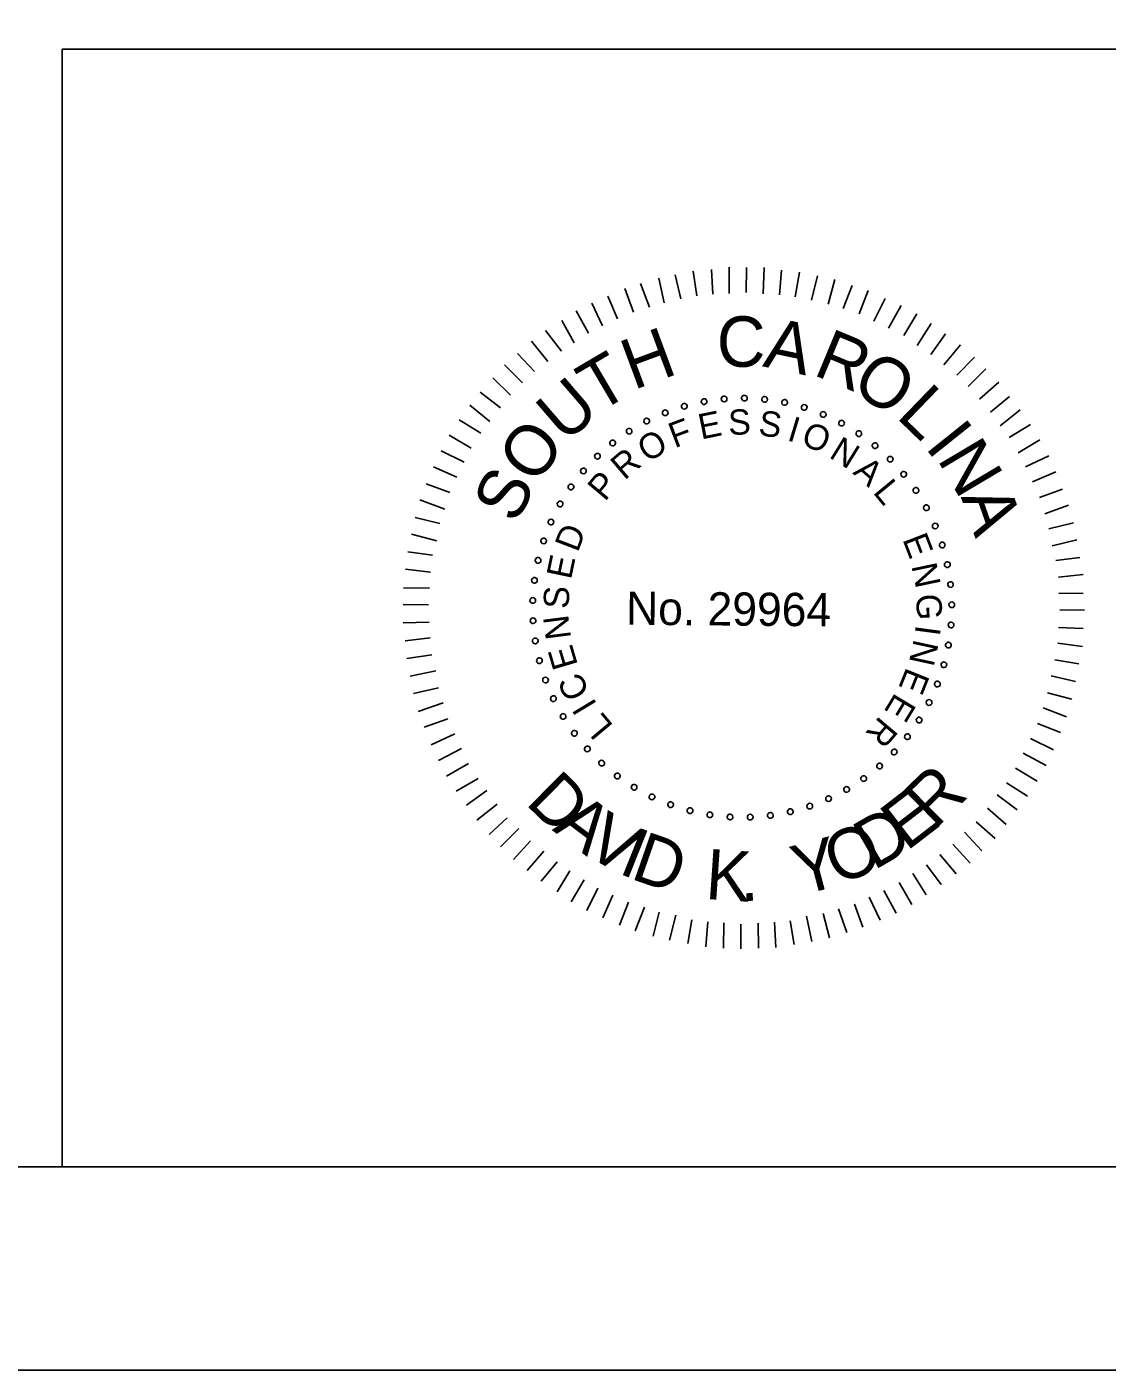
# Model space of a CAD drawing. Extents: x -55.6 to -19.5, y -5.1 to 16.9.
# Drawn here: x -33.037 to -30.378, y -5.092 to -1.787 of the extents above; entities that cross this region are included whole.
import ezdxf

# ---------------------------------------------------------------- set-up
doc = ezdxf.new("R2010")
doc.units = 0
for name, color, linetype in [('BR_BORDER LINES', 7, 'Continuous'), ('BR_TEXT', 7, 'Continuous'), ('Level 31', 7, 'Continuous')]:
    doc.layers.add(name, color=color, linetype=linetype)

msp = doc.modelspace()

# ---------------------------------------------------------------- linework, layer by layer
at = {"layer": 'BR_BORDER LINES'}
for p, q in [((-32.9495, -1.8415), (-27.5843, -1.8415)), ((-32.9495, -4.5916), (-32.9495, -1.8415)), ((-53.7501, -4.5917), (-20.084, -4.5917))]:
    msp.add_line(p, q, dxfattribs=at)
at = {"layer": 'BR_TEXT'}
for p, q in [((-31.3088, -2.4423), (-31.3083, -2.3779)), ((-31.2667, -2.4401), (-31.2662, -2.3783)), ((-31.2247, -2.443), (-31.2224, -2.3786)), ((-31.4686, -2.4658), (-31.4818, -2.4048)), ((-31.4273, -2.4559), (-31.4415, -2.3966)), ((-31.3878, -2.4485), (-31.3967, -2.3875)), ((-31.3483, -2.4445), (-31.3521, -2.3836)), ((-31.1844, -2.4459), (-31.1796, -2.385)), ((-31.1458, -2.4505), (-31.135, -2.3897)), ((-31.1055, -2.4586), (-31.0913, -2.3994)), ((-31.0645, -2.4692), (-31.0485, -2.4084)), ((-31.5443, -2.4884), (-31.5653, -2.4299)), ((-31.5048, -2.4758), (-31.5266, -2.4182)), ((-31.0276, -2.4798), (-31.0057, -2.4225)), ((-30.9883, -2.493), (-30.9663, -2.4348)), ((-31.6201, -2.5221), (-31.6463, -2.4661)), ((-31.5831, -2.5052), (-31.6067, -2.4493)), ((-30.9524, -2.5105), (-30.9245, -2.4549)), ((-30.9165, -2.5279), (-30.8851, -2.4724)), ((-31.69, -2.5636), (-31.7204, -2.5092)), ((-31.6546, -2.5398), (-31.685, -2.4855)), ((-30.8788, -2.5463), (-30.8466, -2.4924)), ((-31.721, -2.5848), (-31.7601, -2.5338)), ((-30.8456, -2.5705), (-30.8117, -2.5167)), ((-30.8123, -2.5923), (-30.7758, -2.5419)), ((-31.7547, -2.6102), (-31.7946, -2.5601)), ((-30.7799, -2.6183), (-30.7392, -2.5688)), ((-31.7876, -2.6348), (-31.8292, -2.5899)), ((-30.7484, -2.6434), (-30.7051, -2.5992)), ((-31.817, -2.662), (-31.8612, -2.6179)), ((-30.7203, -2.6711), (-30.677, -2.6277)), ((-31.8464, -2.6927), (-31.8898, -2.6503)), ((-30.6922, -2.7023), (-30.6447, -2.6606)), ((-31.8715, -2.7243), (-31.921, -2.6852)), ((-30.665, -2.7342), (-30.6184, -2.696)), ((-31.8975, -2.7575), (-31.947, -2.7176)), ((-30.6412, -2.7679), (-30.592, -2.7288)), ((-31.9192, -2.7865), (-31.973, -2.7535)), ((-30.6192, -2.7972), (-30.5666, -2.7651)), ((-31.9436, -2.8232), (-31.9974, -2.791)), ((-30.5972, -2.8343), (-30.5437, -2.803)), ((-31.961, -2.8574), (-32.0174, -2.8295)), ((-30.5794, -2.8688), (-30.5217, -2.8418)), ((-31.9785, -2.8942), (-32.0358, -2.8688)), ((-30.5617, -2.9059), (-30.5049, -2.8814)), ((-31.996, -2.9326), (-32.0541, -2.9107)), ((-30.5449, -2.9446), (-30.4881, -2.9236)), ((-32.0083, -2.9729), (-32.0699, -2.9501)), ((-30.5315, -2.985), (-30.4738, -2.9632)), ((-32.0206, -3.0088), (-32.0815, -2.9937)), ((-30.5215, -3.0212), (-30.4613, -3.0071)), ((-32.0279, -3.0508), (-32.0904, -3.0349)), ((-30.5133, -3.0633), (-30.453, -3.0484)), ((-32.0384, -3.0868), (-32.0993, -3.0785)), ((-30.5049, -3.0994), (-30.4457, -3.0922)), ((-32.0431, -3.1279), (-32.1048, -3.1206)), ((-30.4984, -3.1407), (-30.4374, -3.1343)), ((-32.046, -3.1674), (-32.1103, -3.1668)), ((-30.4971, -3.1802), (-30.437, -3.1807)), ((-32.048, -3.2085), (-32.1107, -3.208)), ((-30.4948, -3.2213), (-30.4339, -3.2218)), ((-32.0467, -3.2515), (-32.111, -3.2526)), ((-30.4977, -3.2642), (-30.4377, -3.2665)), ((-32.0444, -3.2901), (-32.1062, -3.2973)), ((-30.4998, -3.3029), (-30.4389, -3.3111)), ((-32.0404, -3.3313), (-32.1015, -3.3403)), ((-32.0305, -3.3709), (-32.0932, -3.3841)), ((-30.507, -3.344), (-30.4479, -3.3539)), ((-30.5159, -3.3834), (-30.4559, -3.3976)), ((-32.024, -3.413), (-32.085, -3.4271)), ((-30.5248, -3.4254), (-30.4649, -3.4405)), ((-32.0123, -3.45), (-32.0742, -3.4709)), ((-30.5354, -3.4622), (-30.4781, -3.4841)), ((-32.0006, -3.4887), (-32.0591, -3.5097)), ((-30.5495, -3.5007), (-30.493, -3.5226)), ((-31.9837, -3.5257), (-32.0414, -3.5527)), ((-31.9669, -3.5619), (-32.0237, -3.5915)), ((-30.5669, -3.5374), (-30.5105, -3.5653)), ((-31.95, -3.599), (-32.0043, -3.6303)), ((-30.5853, -3.5733), (-30.528, -3.6038)), ((-30.6036, -3.6101), (-30.5506, -3.6423)), ((-31.9263, -3.6361), (-31.9806, -3.6674)), ((-31.905, -3.6654), (-31.9551, -3.7019)), ((-30.6262, -3.6468), (-30.5741, -3.679)), ((-31.8796, -3.6991), (-31.9297, -3.7382)), ((-30.6487, -3.6758), (-30.6001, -3.7131)), ((-31.855, -3.7328), (-31.8991, -3.7736)), ((-30.6731, -3.7091), (-30.6271, -3.7489)), ((-31.826, -3.7588), (-31.871, -3.8039)), ((-30.7008, -3.7423), (-30.6539, -3.7839)), ((-31.7971, -3.789), (-31.8395, -3.835)), ((-30.7579, -3.7976), (-30.7154, -3.8443)), ((-30.7293, -3.7678), (-30.6868, -3.8136)), ((-31.7647, -3.815), (-31.8054, -3.8619)), ((-30.7898, -3.8231), (-30.7499, -3.8706)), ((-31.7314, -3.8411), (-31.7713, -3.8888)), ((-31.7007, -3.8628), (-31.732, -3.9148)), ((-30.8227, -3.8486), (-30.787, -3.8969)), ((-31.6657, -3.8854), (-31.697, -3.9392)), ((-30.89, -3.8918), (-30.8587, -3.9461)), ((-30.8563, -3.8698), (-30.8233, -3.9223)), ((-31.6315, -3.9054), (-31.6586, -3.961)), ((-31.5948, -3.9228), (-31.6193, -3.9784)), ((-30.9641, -3.9281), (-30.9371, -3.9841)), ((-30.9279, -3.9112), (-30.8975, -3.9672)), ((-31.5563, -3.9403), (-31.5782, -3.9968)), ((-31.5169, -3.9527), (-31.5398, -4.0108)), ((-31.481, -3.965), (-31.4952, -4.0241)), ((-31.0398, -3.9566), (-31.0189, -4.0151)), ((-31.0003, -3.9449), (-30.9793, -4.0017)), ((-31.4399, -3.9722), (-31.455, -4.0339)), ((-31.4005, -3.9837), (-31.4104, -4.0419)), ((-31.361, -3.9883), (-31.3659, -4.05)), ((-31.3216, -3.9912), (-31.3221, -4.053)), ((-31.2796, -3.9941), (-31.2801, -4.0551)), ((-31.2375, -3.9919), (-31.2363, -4.0537)), ((-31.1972, -3.9896), (-31.1934, -4.0515)), ((-31.1585, -3.9857), (-31.1487, -4.0441)), ((-31.1181, -3.9748), (-31.1049, -4.0368)), ((-31.0768, -3.9683), (-31.0618, -4.0277))]:
    msp.add_line(p, q, dxfattribs=at)
for centre, start, end in [((-31.3702, -2.7086), 10.6038, 190.6038), ((-31.3702, -2.7086), 190.6038, 10.6038), ((-31.3208, -2.7019), 5.0653, 185.0653), ((-31.3208, -2.7019), 185.0653, 5.0653), ((-31.271, -2.7), 359.5268, 179.5268), ((-31.271, -2.7), 179.5268, 359.5268), ((-31.2213, -2.7029), 353.9884, 173.9884), ((-31.2213, -2.7029), 173.9884, 353.9884), ((-31.1721, -2.7106), 168.4499, 348.4499), ((-31.1721, -2.7106), 348.4499, 168.4499), ((-31.4659, -2.7361), 21.6807, 201.6807), ((-31.4659, -2.7361), 201.6807, 21.6807), ((-31.4187, -2.72), 16.1422, 196.1422), ((-31.4187, -2.72), 196.1422, 16.1422), ((-31.1238, -2.723), 162.9114, 342.9114), ((-31.1238, -2.723), 342.9114, 162.9114), ((-31.077, -2.74), 157.373, 337.373), ((-31.077, -2.74), 337.373, 157.373), ((-31.5545, -2.7814), 32.7576, 212.7576), ((-31.5113, -2.7566), 27.2191, 207.2191), ((-31.5113, -2.7566), 207.2191, 27.2191), ((-31.032, -2.7615), 151.8345, 331.8345), ((-31.032, -2.7615), 331.8345, 151.8345), ((-31.5951, -2.8103), 38.2961, 218.2961), ((-31.5951, -2.8103), 218.2961, 38.2961), ((-31.5545, -2.7814), 212.7576, 32.7576), ((-30.9893, -2.7872), 146.2961, 326.2961), ((-30.9893, -2.7872), 326.2961, 146.2961), ((-31.6327, -2.843), 43.8345, 223.8345), ((-31.6327, -2.843), 223.8345, 43.8345), ((-30.9493, -2.8169), 140.7576, 320.7576), ((-30.9493, -2.8169), 320.7576, 140.7576), ((-31.667, -2.8791), 49.373, 229.373), ((-31.667, -2.8791), 229.373, 49.373), ((-30.9123, -2.8503), 135.2191, 315.2191), ((-30.9123, -2.8503), 315.2191, 135.2191), ((-30.8788, -2.8872), 129.6807, 309.6807), ((-30.8788, -2.8872), 309.6807, 129.6807), ((-31.6977, -2.9184), 54.9114, 234.9114), ((-31.6977, -2.9184), 234.9114, 54.9114), ((-30.8489, -2.9271), 124.1422, 304.1422), ((-30.8489, -2.9271), 304.1422, 124.1422), ((-31.7244, -2.9604), 60.4499, 240.4499), ((-31.7244, -2.9604), 240.4499, 60.4499), ((-30.8231, -2.9697), 118.6038, 298.6038), ((-30.8231, -2.9697), 298.6038, 118.6038), ((-31.747, -3.0049), 65.9884, 245.9884), ((-31.747, -3.0049), 245.9884, 65.9884), ((-30.8014, -3.0146), 293.0653, 113.0653), ((-30.8014, -3.0146), 113.0653, 293.0653), ((-31.7651, -3.0513), 71.5268, 251.5268), ((-31.7651, -3.0513), 251.5268, 71.5268), ((-30.7842, -3.0613), 107.5268, 287.5268), ((-30.7842, -3.0613), 287.5268, 107.5268), ((-31.7787, -3.0992), 77.0653, 257.0653), ((-31.7787, -3.0992), 257.0653, 77.0653), ((-30.7716, -3.1095), 101.9884, 281.9884), ((-30.7716, -3.1095), 281.9884, 101.9884), ((-31.7876, -3.1483), 82.6038, 262.6038), ((-31.7876, -3.1483), 262.6038, 82.6038), ((-30.7638, -3.1587), 96.4499, 276.4499), ((-30.7638, -3.1587), 276.4499, 96.4499), ((-31.7917, -3.1979), 88.1422, 268.1422), ((-31.7917, -3.1979), 268.1422, 88.1422), ((-30.7607, -3.2085), 90.9114, 270.9114), ((-30.7607, -3.2085), 270.9114, 90.9114), ((-31.791, -3.2477), 93.6807, 273.6807), ((-31.791, -3.2477), 273.6807, 93.6807), ((-30.7624, -3.2583), 85.373, 265.373), ((-30.7624, -3.2583), 265.373, 85.373), ((-31.7855, -3.2973), 99.2191, 279.2191), ((-31.7855, -3.2973), 279.2191, 99.2191), ((-30.7689, -3.3077), 79.8345, 259.8345), ((-30.7689, -3.3077), 259.8345, 79.8345), ((-31.7753, -3.346), 104.7576, 284.7576), ((-31.7753, -3.346), 284.7576, 104.7576), ((-30.7801, -3.3562), 74.2961, 254.2961), ((-30.7801, -3.3562), 254.2961, 74.2961), ((-31.7604, -3.3936), 110.2961, 290.2961), ((-31.7604, -3.3936), 290.2961, 110.2961), ((-30.796, -3.4035), 68.7576, 248.7576), ((-30.796, -3.4035), 248.7576, 68.7576), ((-31.7409, -3.4395), 115.8345, 295.8345), ((-31.7409, -3.4395), 295.8345, 115.8345), ((-30.8164, -3.4489), 63.2191, 243.2191), ((-30.8164, -3.4489), 243.2191, 63.2191), ((-31.7171, -3.4833), 121.373, 301.373), ((-31.7171, -3.4833), 301.373, 121.373), ((-30.841, -3.4922), 57.6807, 237.6807), ((-30.841, -3.4922), 237.6807, 57.6807), ((-31.6893, -3.5246), 126.9114, 306.9114), ((-31.6893, -3.5246), 306.9114, 126.9114), ((-30.8698, -3.533), 52.1422, 232.1422), ((-30.8698, -3.533), 232.1422, 52.1422), ((-31.6575, -3.563), 132.4499, 312.4499), ((-31.6575, -3.563), 312.4499, 132.4499), ((-30.9023, -3.5707), 46.6038, 226.6038), ((-30.9023, -3.5707), 226.6038, 46.6038), ((-31.6222, -3.5981), 137.9884, 317.9884), ((-31.6222, -3.5981), 317.9884, 137.9884), ((-30.9383, -3.6052), 41.0653, 221.0653), ((-30.9383, -3.6052), 221.0653, 41.0653), ((-31.5837, -3.6297), 143.5268, 323.5268), ((-31.5837, -3.6297), 323.5268, 143.5268), ((-30.9775, -3.636), 35.5268, 215.5268), ((-30.9775, -3.636), 215.5268, 35.5268), ((-31.5423, -3.6575), 149.0653, 329.0653), ((-31.5423, -3.6575), 329.0653, 149.0653), ((-31.0194, -3.6628), 29.9884, 209.9884), ((-31.0194, -3.6628), 209.9884, 29.9884), ((-31.4984, -3.6811), 154.6038, 334.6038), ((-31.4984, -3.6811), 334.6038, 154.6038), ((-31.4525, -3.7003), 160.1422, 340.1422), ((-31.4525, -3.7003), 340.1422, 160.1422), ((-31.1101, -3.7039), 18.9114, 198.9114), ((-31.1101, -3.7039), 198.9114, 18.9114), ((-31.0638, -3.6855), 24.4499, 204.4499), ((-31.0638, -3.6855), 204.4499, 24.4499), ((-31.4049, -3.7151), 165.6807, 345.6807), ((-31.4049, -3.7151), 345.6807, 165.6807), ((-31.356, -3.7252), 171.2191, 351.2191), ((-31.356, -3.7252), 351.2191, 171.2191), ((-31.3065, -3.7305), 356.7576, 176.7576), ((-31.3065, -3.7305), 176.7576, 356.7576), ((-31.2567, -3.731), 2.2961, 182.2961), ((-31.2567, -3.731), 182.2961, 2.2961), ((-31.207, -3.7267), 7.8345, 187.8345), ((-31.207, -3.7267), 187.8345, 7.8345), ((-31.158, -3.7176), 13.373, 193.373), ((-31.158, -3.7176), 193.373, 13.373)]:
    msp.add_arc(centre, 0.00701, start, end, dxfattribs=at)
at = {"layer": 'Level 31'}
msp.add_lwpolyline([(-55.5834, -5.0916), (-19.5834, -5.0916), (-19.5834, 16.9084), (-55.5834, 16.9084)], close=True, dxfattribs=at)

# ---------------------------------------------------------------- texts
at = {"layer": 'BR_TEXT'}
for s, height, rotation, p in [('C', 0.1241, 359.5482, (-31.3395, -2.6224)), ('A', 0.1241, 348.1981, (-31.2281, -2.6216)), ('H', 0.1241, 20.3637, (-31.5439, -2.6807)), ('R', 0.1241, 337.4344, (-31.1048, -2.6415)), ('T', 0.1241, 30.4992, (-31.6318, -2.7382)), ('O', 0.1239, 326.5869, (-31.0126, -2.6782)), ('U', 0.1241, 40.8022, (-31.713, -2.813)), ('L', 0.1241, 315.9488, (-30.9, -2.746)), ('E', 0.0622, 11.4103, (-31.3775, -2.8019)), ('S', 0.0622, 2.208, (-31.3097, -2.7909)), ('S', 0.0622, 352.6608, (-31.2384, -2.7911)), ('O', 0.1241, 52.0267, (-31.7876, -2.9169)), ('F', 0.0622, 20.6127, (-31.4427, -2.8236)), ('I', 0.0622, 343.1136, (-31.1682, -2.8032)), ('O', 0.0622, 338.4392, (-31.1347, -2.8133)), ('I', 0.1241, 308.6613, (-30.8287, -2.8203)), ('O', 0.0622, 30.8477, (-31.51, -2.8596)), ('N', 0.0622, 328.2042, (-31.0651, -2.8447)), ('N', 0.1241, 300.7037, (-30.7981, -2.8497)), ('R', 0.0622, 40.3949, (-31.5662, -2.9035)), ('A', 0.0622, 318.657, (-31.0061, -2.8847)), ('S', 0.1239, 63.2511, (-31.8329, -3.0125)), ('P', 0.0622, 49.9421, (-31.6143, -2.9561)), ('L', 0.0622, 309.4546, (-30.9564, -2.932)), ('A', 0.1241, 289.4792, (-30.7388, -2.9427)), ('D', 0.0622, 69.0364, (-31.6812, -3.0814)), ('E', 0.0622, 291.049, (-30.8825, -3.0474)), ('E', 0.0622, 78.2388, (-31.6978, -3.148)), ('N', 0.0622, 281.8466, (-30.8603, -3.1124)), ('S', 0.0622, 87.786, (-31.7035, -3.2191)), ('No. 29964', 0.08175, 359.5268, (-31.5624, -3.2575)), ('G', 0.0622, 272.2995, (-30.8486, -3.1827)), ('N', 0.0622, 97.3332, (-31.6973, -3.2901)), ('I', 0.0622, 262.4084, (-30.8489, -3.2565)), ('N', 0.0622, 257.7339, (-30.8535, -3.2911)), ('E', 0.0622, 106.5355, (-31.6803, -3.3566)), ('E', 0.0622, 248.1867, (-30.8715, -3.3601)), ('C', 0.0622, 116.4266, (-31.6504, -3.4241)), ('E', 0.0622, 238.9844, (-30.8994, -3.4228)), ('I', 0.0622, 121.1011, (-31.6324, -3.454)), ('L', 0.0622, 129.9595, (-31.5917, -3.5062)), ('R', 0.0622, 229.782, (-30.9371, -3.4803)), ('D', 0.1236, 315.4053, (-31.8122, -3.6968)), ('R', 0.1236, 44.5947, (-30.8013, -3.7624)), ('E', 0.1236, 37.5339, (-30.872, -3.8163)), ('A', 0.1236, 322.8377, (-31.7456, -3.7624)), ('V', 0.1236, 330.5179, (-31.6685, -3.8206)), ('D', 0.1236, 30.1015, (-30.9529, -3.8632)), ('I', 0.1236, 338.1981, (-31.5842, -3.868)), ('O', 0.1236, 22.4212, (-31.0421, -3.9002)), ('D', 0.1236, 340.7995, (-31.5544, -3.8814)), ('Y', 0.1236, 14.8649, (-31.134, -3.9247)), ('K', 0.1236, 356.098, (-31.3691, -3.932)), ('.', 0.1236, 3.1588, (-31.2805, -3.9383))]:
    msp.add_text(s, height=height, rotation=rotation, dxfattribs=at).set_placement(p)

doc.saveas('drawing.dxf')
